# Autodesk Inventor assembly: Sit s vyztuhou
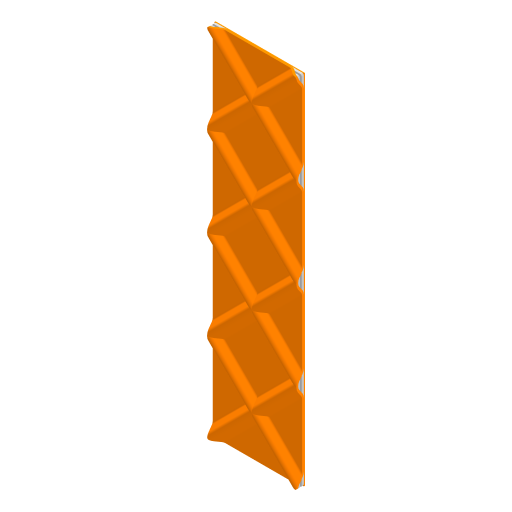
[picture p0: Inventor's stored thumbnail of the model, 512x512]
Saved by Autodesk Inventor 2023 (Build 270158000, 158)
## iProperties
Created: 2025-03
Part Number: Sit s vyztuhou
Document SubType Name: Assembly
Designer: tomik
Author: tomik
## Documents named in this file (4)
- C:\Users\tomik\Desktop\Růčka_Tomáš_přílohy\Vyztužení\Síť žeber s kanálky\Sit s kanalky.iam
- C:\Users\tomik\Desktop\Růčka_Tomáš_přílohy\Vyztužení\Síť žeber s kanálky\Spodni tkanina 50x200.ipt
- C:\Users\tomik\Desktop\Růčka_Tomáš_přílohy\Vyztužení\Síť žeber s kanálky\Sit zeber s kanalky.ipt
- C:\Users\tomik\Desktop\Růčka_Tomáš_přílohy\Vyztužení\Síť žeber\Horni_tkanina.ipt
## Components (3 placed, 3 different names)
1. Spodni tkanina 50x200:1 — Proti sobě:1, Proti sobě:2, Stejný směr:1, Proti sobě:3, Proti sobě:4, Proti sobě:5, Proti sobě:9, Proti sobě:10, Proti sobě:11
2. Sit zeber s kanalky:1 — Proti sobě:3, Proti sobě:4, Proti sobě:5
3. Horni_tkanina:1 — Proti sobě:9, Proti sobě:10, Proti sobě:11
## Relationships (9: Mate 8, Flush 1)
- Proti sobě:1 [Mate]: Spodni tkanina 50x200:1
- Proti sobě:2 [Mate]: Spodni tkanina 50x200:1
- Stejný směr:1 [Flush]: Spodni tkanina 50x200:1
- Proti sobě:3 [Mate]: Spodni tkanina 50x200:1 ↔ Sit zeber s kanalky:1
- Proti sobě:4 [Mate]: Spodni tkanina 50x200:1 ↔ Sit zeber s kanalky:1
- Proti sobě:5 [Mate]: Spodni tkanina 50x200:1 ↔ Sit zeber s kanalky:1
- Proti sobě:9 [Mate]: Spodni tkanina 50x200:1 ↔ Horni_tkanina:1
- Proti sobě:10 [Mate]: Spodni tkanina 50x200:1 ↔ Horni_tkanina:1
- Proti sobě:11 [Mate]: Spodni tkanina 50x200:1 ↔ Horni_tkanina:1
